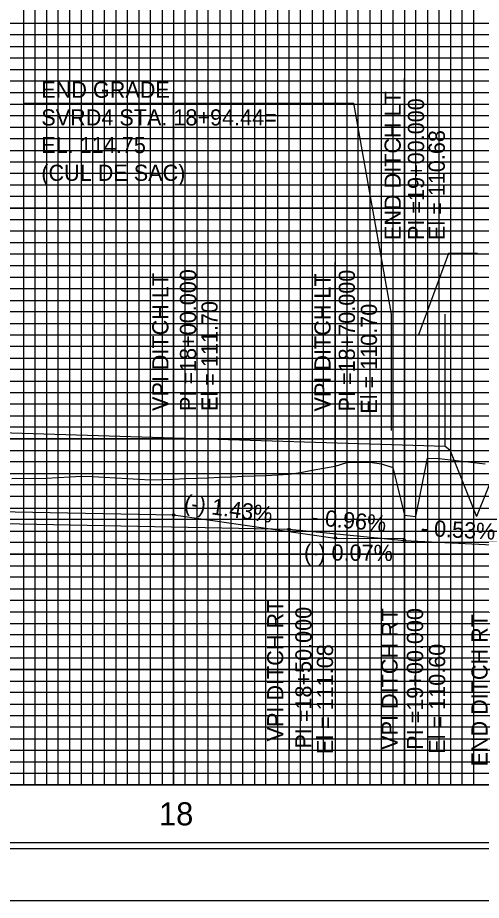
# Model space of a CAD drawing. Extents: x 2345490 to 2436403, y 465165 to 573888.
# Drawn here: x 2382499.3 to 2382700.1, y 495042.6 to 495425.1 of the extents above; entities that cross this region are included whole.
import ezdxf

# ---------------------------------------------------------------- set-up
doc = ezdxf.new("R2010")
doc.units = 0
for name, color, linetype in [('Old_Level_1', 7, 'Continuous'), ('Old_Level_18', 7, 'Continuous'), ('Old_Level_2', 7, 'Continuous'), ('Old_Level_3', 7, 'Continuous'), ('Old_Level_41', 7, 'Continuous'), ('Old_Level_42', 7, 'Continuous'), ('Old_Level_43', 7, 'Continuous'), ('Old_Level_50', 7, 'Continuous'), ('Old_Level_51', 7, 'Continuous'), ('Old_Level_57', 7, 'Continuous'), ('Old_Level_62', 7, 'Continuous'), ('Old_Level_63', 7, 'Continuous')]:
    doc.layers.add(name, color=color, linetype=linetype)

msp = doc.modelspace()

# ---------------------------------------------------------------- linework, layer by layer
at = {"layer": 'Old_Level_1'}
msp.add_lwpolyline([(2382496.799, 495225.484), (2382501.799, 495225.5545), (2382506.799, 495225.3665), (2382511.799, 495225.63425), (2382516.799, 495225.92225), (2382521.799, 495226.21), (2382526.799, 495226.498), (2382531.799, 495226.36925), (2382536.799, 495226.062), (2382541.799, 495225.75475), (2382546.799, 495225.4475), (2382551.799, 495225.14025), (2382556.799, 495224.83325), (2382561.799, 495225.01575), (2382566.799, 495225.20975), (2382571.799, 495225.40375), (2382576.799, 495225.5975), (2382581.799, 495225.7915), (2382586.799, 495225.9855), (2382591.799, 495226.1795), (2382596.799, 495226.3735), (2382601.799, 495226.56725), (2382606.799, 495226.76125), (2382611.799, 495226.9785), (2382616.799, 495227.367), (2382621.799, 495228.1065), (2382626.799, 495229.01525), (2382631.799, 495229.92425), (2382636.799, 495230.833), (2382641.799, 495232.434), (2382646.799, 495232.5515), (2382651.799, 495232.44925), (2382656.799, 495231.79525), (2382661.799, 495230.1425), (2382666.799, 495209.488), (2382671.799, 495208.963), (2382676.799, 495234.20225), (2382681.799, 495234.11025), (2382686.799, 495233.52925), (2382691.799, 495232.94825), (2382696.799, 495232.36725), (2382701.799, 495231.78625)], dxfattribs=at)
at = {"layer": 'Old_Level_18'}
msp.add_lwpolyline([(2383216.79875, 496117.6345), (2381716.79875, 496117.6345), (2381716.79875, 495067.6345), (2383216.79875, 495067.6345)], close=True, dxfattribs=at)
at = {"layer": 'Old_Level_2'}
for p, q in [((2382501.71825, 495388.04225), (2382644.91275, 495388.04225)), ((2382661.239, 495296.665), (2382644.91275, 495388.04225)), ((2382685.85575, 495322.94375), (2382672.849, 495287.62975)), ((2382698.42075, 495322.94375), (2382685.85575, 495322.94375)), ((2382661.239, 495246.3065), (2382661.239, 495296.665)), ((2382684.459, 495239.3945), (2382684.459, 495296.665)), ((2382661.239, 495287.62975), (2382684.459, 495287.62975)), ((2382491.799, 495245.3335), (2382661.239, 495240.1345)), ((2382661.239, 495240.1345), (2382684.459, 495239.422)), ((2382684.459, 495239.422), (2382686.459, 495237.8345)), ((2382686.459, 495237.8345), (2382698.0075, 495208.963)), ((2382706.89975, 495231.1935), (2382698.0075, 495208.963))]:
    msp.add_line(p, q, dxfattribs=at)
at = {"layer": 'Old_Level_3'}
for p, q in [((2382666.799, 495199.4345), (2382666.799, 495398.88899)), ((2382566.799, 495209.6345), (2382566.799, 495319.81585)), ((2382636.799, 495199.6345), (2382636.799, 495319.097)), ((2382266.799, 495215.6345), (2382566.799, 495209.6345)), ((2382566.799, 495209.6345), (2382636.799, 495199.6345)), ((2382616.799, 495203.4345), (2382616.799, 495108.11368)), ((2382636.799, 495199.6345), (2382666.799, 495199.4345)), ((2382666.799, 495198.6345), (2382666.799, 495104.87885))]:
    msp.add_line(p, q, dxfattribs=at)
msp.add_lwpolyline([(2382266.799, 495210.4345), (2382616.799, 495203.4345), (2382666.799, 495198.6345), (2382704.799, 495196.6345)], dxfattribs=at)
for centre in [(2382566.799, 495209.6345), (2382616.799, 495203.4345), (2382636.799, 495199.6345), (2382666.799, 495198.6345)]:
    msp.add_circle(centre, 0.5, dxfattribs=at)
at = {"layer": 'Old_Level_41'}
msp.add_line((2383216.79875, 495092.6345), (2381716.79875, 495092.6345), dxfattribs=at)
for points in [[(2382466.79875, 496117.6345), (2382466.79875, 495092.6345), (2382516.79875, 495092.6345), (2382516.79875, 496117.6345)], [(2382541.79875, 496117.6345), (2382541.79875, 495092.6345), (2382591.79875, 495092.6345), (2382591.79875, 496117.6345)], [(2382566.79875, 496117.6345), (2382566.79875, 495092.6345), (2382616.79875, 495092.6345), (2382616.79875, 496117.6345)], [(2382641.79875, 496117.6345), (2382641.79875, 495092.6345), (2382691.79875, 495092.6345), (2382691.79875, 496117.6345)], [(2382666.79875, 496117.6345), (2382666.79875, 495092.6345), (2382716.79875, 495092.6345), (2382716.79875, 496117.6345)], [(2383216.79875, 495417.6345), (2381716.79875, 495417.6345), (2381716.79875, 495367.6345), (2383216.79875, 495367.6345)], [(2383216.79875, 495342.6345), (2381716.79875, 495342.6345), (2381716.79875, 495392.6345), (2383216.79875, 495392.6345)], [(2383216.79875, 495317.6345), (2381716.79875, 495317.6345), (2381716.79875, 495267.6345), (2383216.79875, 495267.6345)], [(2383216.79875, 495217.6345), (2381716.79875, 495217.6345), (2381716.79875, 495167.6345), (2383216.79875, 495167.6345)], [(2383216.79875, 495142.6345), (2381716.79875, 495142.6345), (2381716.79875, 495192.6345), (2383216.79875, 495192.6345)], [(2383216.79875, 495117.6345), (2381716.79875, 495117.6345)]]:
    msp.add_lwpolyline(points, dxfattribs=at)
at = {"layer": 'Old_Level_42'}
msp.add_lwpolyline([(2383216.79875, 495242.6345), (2381716.79875, 495242.6345), (2381716.79875, 495292.6345), (2383216.79875, 495292.6345)], dxfattribs=at)
at = {"layer": 'Old_Level_43'}
for points in [[(2382501.79875, 496117.6345), (2382501.79875, 495092.6345), (2382506.79875, 495092.6345), (2382506.79875, 496117.6345)], [(2382511.79875, 496117.6345), (2382511.79875, 495092.6345), (2382521.79875, 495092.6345), (2382521.79875, 496117.6345)], [(2382526.79875, 496117.6345), (2382526.79875, 495092.6345), (2382531.79875, 495092.6345), (2382531.79875, 496117.6345)], [(2382536.79875, 496117.6345), (2382536.79875, 495092.6345), (2382546.79875, 495092.6345), (2382546.79875, 496117.6345)], [(2382551.79875, 496117.6345), (2382551.79875, 495092.6345), (2382556.79875, 495092.6345), (2382556.79875, 496117.6345)], [(2382561.79875, 496117.6345), (2382561.79875, 495092.6345), (2382571.79875, 495092.6345), (2382571.79875, 496117.6345)], [(2382576.79875, 496117.6345), (2382576.79875, 495092.6345), (2382581.79875, 495092.6345), (2382581.79875, 496117.6345)], [(2382586.79875, 496117.6345), (2382586.79875, 495092.6345), (2382596.79875, 495092.6345), (2382596.79875, 496117.6345)], [(2382601.79875, 496117.6345), (2382601.79875, 495092.6345), (2382606.79875, 495092.6345), (2382606.79875, 496117.6345)], [(2382611.79875, 496117.6345), (2382611.79875, 495092.6345), (2382621.79875, 495092.6345), (2382621.79875, 496117.6345)], [(2382626.79875, 496117.6345), (2382626.79875, 495092.6345), (2382631.79875, 495092.6345), (2382631.79875, 496117.6345)], [(2382636.79875, 496117.6345), (2382636.79875, 495092.6345), (2382646.79875, 495092.6345), (2382646.79875, 496117.6345)], [(2382651.79875, 496117.6345), (2382651.79875, 495092.6345), (2382656.79875, 495092.6345), (2382656.79875, 496117.6345)], [(2382661.79875, 496117.6345), (2382661.79875, 495092.6345), (2382671.79875, 495092.6345), (2382671.79875, 496117.6345)], [(2382676.79875, 496117.6345), (2382676.79875, 495092.6345), (2382681.79875, 495092.6345), (2382681.79875, 496117.6345)], [(2382686.79875, 496117.6345), (2382686.79875, 495092.6345), (2382696.79875, 495092.6345), (2382696.79875, 496117.6345)], [(2383166.79875, 495422.6345), (2381766.79875, 495422.6345), (2381766.79875, 495412.6345), (2383166.79875, 495412.6345)], [(2383166.79875, 495407.6345), (2381766.79875, 495407.6345), (2381766.79875, 495402.6345), (2383166.79875, 495402.6345)], [(2383166.79875, 495397.6345), (2381766.79875, 495397.6345), (2381766.79875, 495387.6345), (2383166.79875, 495387.6345)], [(2383166.79875, 495382.6345), (2381766.79875, 495382.6345), (2381766.79875, 495377.6345), (2383166.79875, 495377.6345)], [(2383166.79875, 495372.6345), (2381766.79875, 495372.6345), (2381766.79875, 495362.6345), (2383166.79875, 495362.6345)], [(2383166.79875, 495357.6345), (2381766.79875, 495357.6345), (2381766.79875, 495352.6345), (2383166.79875, 495352.6345)], [(2383166.79875, 495347.6345), (2381766.79875, 495347.6345), (2381766.79875, 495337.6345), (2383166.79875, 495337.6345)], [(2383166.79875, 495332.6345), (2381766.79875, 495332.6345), (2381766.79875, 495327.6345), (2383166.79875, 495327.6345)], [(2383166.79875, 495322.6345), (2381766.79875, 495322.6345), (2381766.79875, 495312.6345), (2383166.79875, 495312.6345)], [(2383166.79875, 495307.6345), (2381766.79875, 495307.6345), (2381766.79875, 495302.6345), (2383166.79875, 495302.6345)], [(2383166.79875, 495297.6345), (2381766.79875, 495297.6345)], [(2381766.79875, 495287.6345), (2383166.79875, 495287.6345)], [(2383166.79875, 495282.6345), (2381766.79875, 495282.6345), (2381766.79875, 495277.6345), (2383166.79875, 495277.6345)], [(2383166.79875, 495272.6345), (2381766.79875, 495272.6345)], [(2381766.79875, 495262.6345), (2383166.79875, 495262.6345)], [(2383166.79875, 495257.6345), (2381766.79875, 495257.6345), (2381766.79875, 495252.6345), (2383166.79875, 495252.6345)], [(2383166.79875, 495247.6345), (2381766.79875, 495247.6345), (2381766.79875, 495237.6345), (2383166.79875, 495237.6345)], [(2383166.79875, 495232.6345), (2381766.79875, 495232.6345), (2381766.79875, 495227.6345), (2383166.79875, 495227.6345)], [(2383166.79875, 495222.6345), (2381766.79875, 495222.6345), (2381766.79875, 495212.6345), (2383166.79875, 495212.6345)], [(2383166.79875, 495207.6345), (2381766.79875, 495207.6345), (2381766.79875, 495202.6345), (2383166.79875, 495202.6345)], [(2383166.79875, 495197.6345), (2381766.79875, 495197.6345), (2381766.79875, 495187.6345), (2383166.79875, 495187.6345)], [(2383166.79875, 495182.6345), (2381766.79875, 495182.6345), (2381766.79875, 495177.6345), (2383166.79875, 495177.6345)], [(2383166.79875, 495172.6345), (2381766.79875, 495172.6345), (2381766.79875, 495162.6345), (2383166.79875, 495162.6345)], [(2383166.79875, 495157.6345), (2381766.79875, 495157.6345), (2381766.79875, 495152.6345), (2383166.79875, 495152.6345)], [(2383166.79875, 495147.6345), (2381766.79875, 495147.6345), (2381766.79875, 495137.6345), (2383166.79875, 495137.6345)], [(2383166.79875, 495132.6345), (2381766.79875, 495132.6345), (2381766.79875, 495127.6345), (2383166.79875, 495127.6345)], [(2383166.79875, 495122.6345), (2381766.79875, 495122.6345), (2381766.79875, 495112.6345), (2383166.79875, 495112.6345)], [(2383166.79875, 495107.6345), (2381766.79875, 495107.6345), (2381766.79875, 495102.6345), (2383166.79875, 495102.6345)], [(2383166.79875, 495097.6345), (2381766.79875, 495097.6345)]]:
    msp.add_lwpolyline(points, dxfattribs=at)
at = {"layer": 'Old_Level_50'}
msp.add_lwpolyline([(2383229.29875, 496120.1845), (2381562.79875, 496120.1845), (2381562.79875, 495065.0845), (2383229.29875, 495065.0845)], close=True, dxfattribs=at)
at = {"layer": 'Old_Level_51'}
msp.add_lwpolyline([(2383233.79875, 496142.6345), (2381549.79875, 496142.6345), (2381549.79875, 495042.6345), (2383233.79875, 495042.6345)], close=True, dxfattribs=at)
at = {"layer": 'Old_Level_57'}
for p, q in [((2381716.79925, 495392.63475), (2382966.79875, 495392.63475)), ((2382566.79875, 495092.63475), (2382566.79875, 495392.63475)), ((2382566.79875, 495092.63475), (2382566.79875, 495392.63475)), ((2382566.79875, 495092.63475), (2382566.79875, 495392.63475)), ((2382566.79875, 495092.63475), (2382566.79875, 495392.63475)), ((2382566.79875, 495092.63475), (2382566.79875, 495392.63475)), ((2382566.79875, 495092.73475), (2382566.79875, 495392.63475)), ((2382566.79875, 495092.73475), (2382566.79875, 495392.63475)), ((2382566.79875, 495092.73475), (2382566.79875, 495392.63475)), ((2382566.79875, 495092.73475), (2382566.79875, 495392.63475)), ((2382566.79875, 495092.73475), (2382566.79875, 495392.63475)), ((2382666.79875, 495092.63475), (2382666.79875, 495392.63475)), ((2382666.79875, 495092.63475), (2382666.79875, 495392.63475)), ((2382666.79875, 495092.63475), (2382666.79875, 495392.63475)), ((2382666.79875, 495092.63475), (2382666.79875, 495392.63475)), ((2382666.79875, 495092.63475), (2382666.79875, 495392.63475)), ((2382666.79875, 495092.73475), (2382666.79875, 495392.63475)), ((2382666.79875, 495092.73475), (2382666.79875, 495392.63475)), ((2382666.79875, 495092.73475), (2382666.79875, 495392.63475)), ((2382666.79875, 495092.73475), (2382666.79875, 495392.63475)), ((2382666.79875, 495092.73475), (2382666.79875, 495392.63475)), ((2381716.79925, 495342.63475), (2382966.79875, 495342.63475)), ((2381716.79925, 495292.63475), (2382966.79875, 495292.63475)), ((2381716.79925, 495242.63475), (2382966.79875, 495242.63475)), ((2381716.79925, 495192.73475), (2382966.79875, 495192.73475)), ((2381716.79925, 495192.63475), (2382966.79875, 495192.63475)), ((2381816.79925, 495192.73475), (2382966.79875, 495192.73475)), ((2381816.79925, 495192.63475), (2382966.79875, 495192.63475)), ((2381916.79925, 495192.73475), (2382966.79875, 495192.73475)), ((2381916.79925, 495192.63475), (2382966.79875, 495192.63475)), ((2382016.79925, 495192.73475), (2382966.79875, 495192.73475)), ((2382016.79925, 495192.63475), (2382966.79875, 495192.63475)), ((2382116.79925, 495192.73475), (2382966.79875, 495192.73475)), ((2382116.79925, 495192.63475), (2382966.79875, 495192.63475)), ((2382216.79925, 495192.73475), (2382966.79875, 495192.73475)), ((2382216.79925, 495192.63475), (2382966.79875, 495192.63475)), ((2382316.79925, 495192.73475), (2382966.79875, 495192.73475)), ((2382316.79925, 495192.63475), (2382966.79875, 495192.63475)), ((2382416.79925, 495192.73475), (2382966.79875, 495192.73475)), ((2382416.79925, 495192.63475), (2382966.79875, 495192.63475)), ((2382516.79925, 495192.73475), (2382966.79875, 495192.73475)), ((2382516.79925, 495192.63475), (2382966.79875, 495192.63475)), ((2382616.79925, 495192.73475), (2382966.79875, 495192.73475)), ((2382616.79925, 495192.63475), (2382966.79875, 495192.63475)), ((2381716.799, 495142.73475), (2382966.79875, 495142.73475)), ((2381716.799, 495142.63475), (2382966.79875, 495142.63475)), ((2381816.799, 495142.73475), (2382966.79875, 495142.73475)), ((2381816.799, 495142.63475), (2382966.79875, 495142.63475)), ((2381916.799, 495142.73475), (2382966.79875, 495142.73475)), ((2381916.799, 495142.63475), (2382966.79875, 495142.63475)), ((2382016.799, 495142.73475), (2382966.79875, 495142.73475)), ((2382016.799, 495142.63475), (2382966.79875, 495142.63475)), ((2382116.799, 495142.73475), (2382966.79875, 495142.73475)), ((2382116.799, 495142.63475), (2382966.79875, 495142.63475)), ((2382216.799, 495142.73475), (2382966.79875, 495142.73475)), ((2382216.799, 495142.63475), (2382966.79875, 495142.63475)), ((2382316.799, 495142.73475), (2382966.79875, 495142.73475)), ((2382316.799, 495142.63475), (2382966.79875, 495142.63475)), ((2382416.799, 495142.73475), (2382966.79875, 495142.73475)), ((2382416.799, 495142.63475), (2382966.79875, 495142.63475)), ((2382516.799, 495142.73475), (2382966.79875, 495142.73475)), ((2382516.799, 495142.63475), (2382966.79875, 495142.63475)), ((2382616.799, 495142.73475), (2382966.79875, 495142.73475)), ((2382616.799, 495142.63475), (2382966.79875, 495142.63475)), ((2381716.79925, 495092.73475), (2382966.79875, 495092.73475)), ((2381816.79925, 495092.73475), (2382966.79875, 495092.73475)), ((2381916.79925, 495092.73475), (2382966.79875, 495092.73475)), ((2382016.79925, 495092.73475), (2382966.79875, 495092.73475)), ((2382116.79925, 495092.73475), (2382966.79875, 495092.73475)), ((2382216.79925, 495092.73475), (2382966.79875, 495092.73475)), ((2382316.79925, 495092.73475), (2382966.79875, 495092.73475)), ((2382416.79925, 495092.73475), (2382966.79875, 495092.73475)), ((2382516.79925, 495092.73475), (2382966.79875, 495092.73475)), ((2382616.79925, 495092.73475), (2382966.79875, 495092.73475)), ((2381716.79925, 495092.63475), (2382966.79875, 495092.63475)), ((2381816.79925, 495092.63475), (2382966.79875, 495092.63475)), ((2381916.79925, 495092.63475), (2382966.79875, 495092.63475)), ((2382016.79925, 495092.63475), (2382966.79875, 495092.63475)), ((2382116.79925, 495092.63475), (2382966.79875, 495092.63475)), ((2382216.79925, 495092.63475), (2382966.79875, 495092.63475)), ((2382316.79925, 495092.63475), (2382966.79875, 495092.63475)), ((2382416.79925, 495092.63475), (2382966.79875, 495092.63475)), ((2382516.79925, 495092.63475), (2382966.79875, 495092.63475)), ((2382616.79925, 495092.63475), (2382966.79875, 495092.63475))]:
    msp.add_line(p, q, dxfattribs=at)
at = {"layer": 'Old_Level_63'}
msp.add_line((2381766.79875, 495092.6345), (2382911.238, 495092.6345), dxfattribs=at)

# ---------------------------------------------------------------- texts
at = {"layer": 'Old_Level_2'}
for s, height, p in [('END GRADE', 7.000001, (2382509.505, 495390.414)), ('SVRD4 STA. 18+94.44=', 7.0000005, (2382509.505, 495378.414)), ('EL. 114.75', 7.000001, (2382509.505, 495366.414)), ('(CUL DE SAC)', 7.0000005, (2382509.505, 495354.414))]:
    msp.add_text(s, height=height, dxfattribs=at).set_placement(p)
at = {"layer": 'Old_Level_3'}
for s, height, rotation, p in [('END DITCH LT', 7.0000005, 90, (2382665.19555, 495328.77769)), ('PI =19+00.000', 7.0000005, 90, (2382675.31272, 495328.77769)), ('El = 110.68', 7.0000005, 90, (2382684.28928, 495328.77769)), ('PI =18+00.000', 7.0000005, 90, (2382576.54024, 495254.70075)), ('PI =18+70.000', 7.0000005, 90, (2382645.34215, 495254.4964)), ('VPI DITCH LT', 7.0000005, 90, (2382564.55938, 495254.70075)), ('VPI DITCH LT', 7.0000005, 90, (2382634.799, 495254.4964)), ('El = 111.70', 7.0000005, 90, (2382585.86292, 495254.70075)), ('El = 110.70', 7.0000005, 90, (2382654.90445, 495253.53793)), ('(-) 1.43%', 7.000001, 351.8698972, (2382571.0593, 495211.64003)), ('- 0.96%', 7.000001, 354.5164083, (2382626.45127, 495205.37383)), ('- 0.53%', 7.000001, 356.9872111, (2382673.76449, 495200.60017)), ('(-) 0.07%', 7.000001, 359.6180333, (2382623.2579, 495189.93853)), ('VPI DITCH RT', 7.0000005, 90, (2382614.31977, 495111.50629)), ('PI =18+50.000', 7.0000005, 90, (2382626.54024, 495108.39127)), ('VPI DITCH RT', 7.0000005, 90, (2382663.84053, 495107.88087)), ('PI =19+00.000', 7.0000005, 90, (2382674.86292, 495107.88087)), ('END DITCH RT', 7.0000005, 90, (2382702.799, 495100.6328)), ('El = 111.08', 7.0000005, 90, (2382635.86292, 495105.9951)), ('El = 110.60', 7.0000005, 90, (2382684.42521, 495106.20355))]:
    msp.add_text(s, height=height, rotation=rotation, dxfattribs=at).set_placement(p)
at = {"layer": 'Old_Level_62'}
msp.add_text('18', height=10.000001, dxfattribs=at).set_placement((2382560.46425, 495075.1345))

doc.saveas('drawing.dxf')
